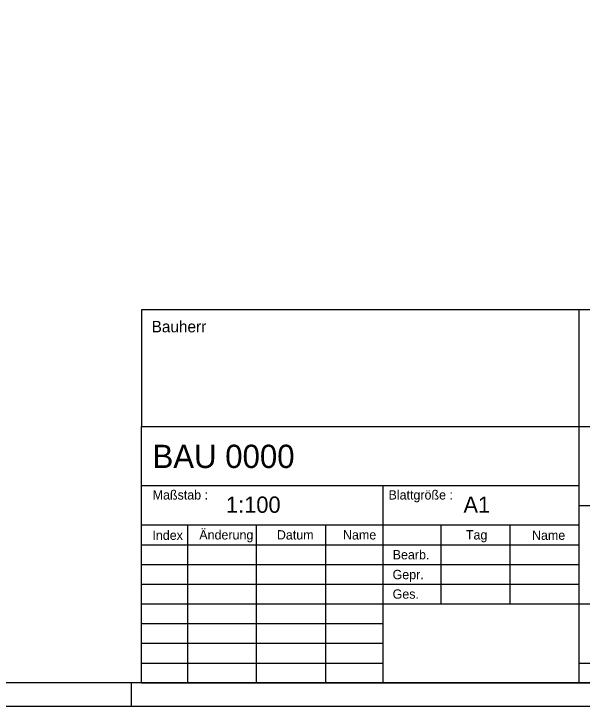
# Model space of a CAD drawing. Extents: x 0 to 84.1, y 0 to 59.4.
# Drawn here: x 63.08 to 75.27, y 0 to 14.85 of the extents above; entities that cross this region are included whole.
import ezdxf

# ---------------------------------------------------------------- set-up
doc = ezdxf.new("R2010")
doc.units = 0
doc.layers.add('90_Plankopf', color=7, linetype='Continuous')

msp = doc.modelspace()

# ---------------------------------------------------------------- linework, layer by layer
at = {"layer": '90_Plankopf'}
for p, q in [((83.6, 8.499), (65.812, 8.499)), ((65.812, 8.499), (65.812, 5.999)), ((75.2, 5.999), (75.2, 8.499)), ((65.812, 5.999), (83.6, 5.999)), ((65.812, 0.5), (65.812, 5.999)), ((65.812, 5.999), (83.6, 5.999)), ((75.2, 0.5), (75.2, 5.999)), ((65.812, 4.73), (75.2, 4.73)), ((71, 0.5), (71, 4.73)), ((75.2, 4.307), (83.6, 4.307)), ((65.812, 3.887), (75.2, 3.887)), ((66.8, 3.884), (66.8, 0.5)), ((68.283, 0.5), (68.283, 3.884)), ((69.765, 0.5), (69.765, 3.884)), ((72.235, 3.884), (72.235, 2.192)), ((73.718, 2.192), (73.718, 3.884)), ((65.812, 3.463), (75.2, 3.463)), ((65.812, 3.038), (75.2, 3.038)), ((65.812, 2.615), (75.2, 2.615)), ((65.812, 2.192), (75.2, 2.192)), ((65.812, 2.192), (75.2, 2.192)), ((71, 2.192), (75.2, 2.192)), ((75.2, 2.192), (83.6, 2.192)), ((71, 1.769), (65.812, 1.769)), ((71, 1.346), (65.812, 1.346)), ((65.812, 0.923), (71, 0.923)), ((75.2, 0.923), (83.6, 0.923)), ((65.6, 0), (65.6, 0.5)), ((83.6, 0.5), (65.812, 0.5)), ((65.812, 0.5), (71, 0.5)), ((66.98, 0.5), (83.6, 0.5)), ((66.98, 0.5), (83.6, 0.5))]:
    msp.add_line(p, q, dxfattribs=at)
for points in [[(0, 0), (84.1, 0), (84.1, 59.4), (0, 59.4)], [(2.5, 58.9), (83.6, 58.9), (83.6, 0.5), (2.5, 0.5)]]:
    msp.add_lwpolyline(points, close=True, dxfattribs=at)

# ---------------------------------------------------------------- texts
for s, height, p in [('Bauherr', 0.2464, (66.03, 8.018)), ('BAU 0000      ', 0.5, (66.049, 5.108)), ('Maßstab :', 0.2, (66.052, 4.432)), ('Blattgröße :', 0.19999, (71.112, 4.432)), ('1:100    ', 0.35, (67.626, 4.147)), ('A1       ', 0.35, (72.72, 4.147)), ('Index', 0.2, (66.047, 3.567)), ('Änderung', 0.2, (67.053, 3.575)), ('Datum', 0.2, (68.717, 3.575)), ('Name', 0.2, (70.135, 3.575)), ('Tag', 0.2, (72.772, 3.575)), ('Name', 0.2, (74.189, 3.567)), ('Bearb.', 0.2, (71.201, 3.149)), ('Gepr.', 0.2, (71.199, 2.723)), ('Ges.', 0.2, (71.2, 2.305))]:
    msp.add_text(s, height=height, dxfattribs=at).set_placement(p)

doc.saveas('drawing.dxf')
